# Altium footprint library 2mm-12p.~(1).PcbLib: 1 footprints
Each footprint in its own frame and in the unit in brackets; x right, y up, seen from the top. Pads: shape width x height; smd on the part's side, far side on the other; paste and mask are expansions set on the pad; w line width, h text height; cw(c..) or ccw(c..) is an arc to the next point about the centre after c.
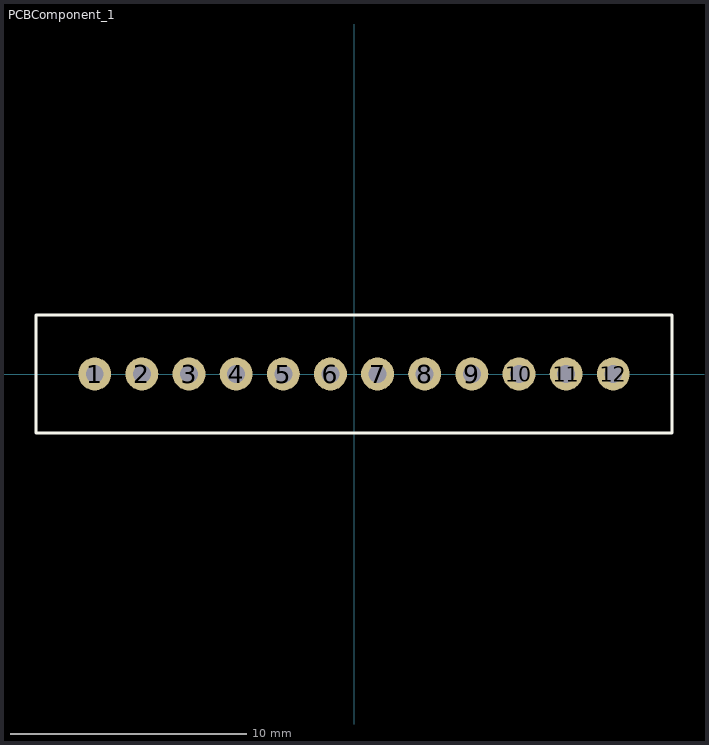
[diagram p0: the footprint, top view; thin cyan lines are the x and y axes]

## PCBComponent_1 [mil]
pads (12):
  round 55 hole 30: 1(-433.07,0) 2(-354.33,0) 3(-275.59,0) 4(-196.85,0) 5(-118.11,0) 6(-39.37,0) 7(39.37,0) 8(118.11,0) 9(196.85,0) 10(275.59,0) 11(354.33,0) 12(433.07,0)
Top Overlay:
  lines w5: -531.5,-98.43 -531.5,-78.74 -531.5,98.43 511.81,98.43 531.5,98.43 531.5,-98.43 -531.5,-98.43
